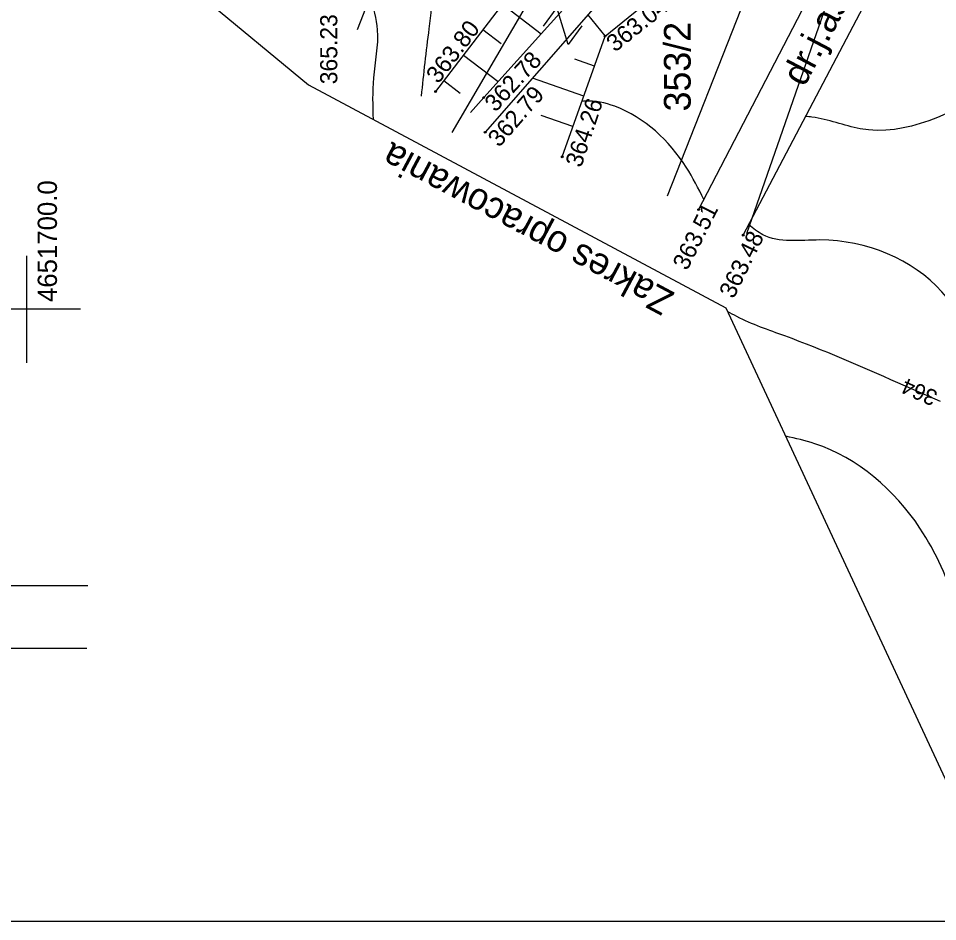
# Model space of a CAD drawing. Extents: x 4635329 to 4651863, y 5356628 to 5367582.
# Drawn here: x 4651136.61 to 4651179.57, y 5356627.73 to 5356669.94 of the extents above; entities that cross this region are included whole.
import ezdxf

# ---------------------------------------------------------------- set-up
doc = ezdxf.new("R2010")
doc.units = 0
for name, color, linetype in [('Level 1', 7, 'Continuous'), ('Level 13', 7, 'Continuous'), ('Level 20', 7, 'Continuous'), ('Level 21', 7, 'Continuous'), ('Level 4', 7, 'Continuous'), ('Level 44', 7, 'Continuous'), ('Level 45', 7, 'Continuous'), ('Level 46', 7, 'Continuous'), ('Level 47', 7, 'Continuous'), ('Level 48', 7, 'Continuous'), ('Level 5', 7, 'Continuous'), ('Level 50', 7, 'Continuous'), ('Level 53', 7, 'Continuous'), ('Level 58', 7, 'Continuous'), ('Level 6', 7, 'Continuous'), ('Level 60', 7, 'Continuous')]:
    doc.layers.add(name, color=color, linetype=linetype)

msp = doc.modelspace()

# ---------------------------------------------------------------- linework, layer by layer
at = {"layer": 'Level 1'}
for p, q in [((4651116.718, 5356694.556), (4651150.17, 5356666.828)), ((4651150.17, 5356666.828), (4651169.678, 5356656.408)), ((4651169.678, 5356656.408), (4651180.231, 5356633.731))]:
    msp.add_line(p, q, dxfattribs=at)
at = {"layer": 'Level 13'}
for p, q in [((4651124.206, 5356643.431), (4651139.857, 5356643.431)), ((4651124.168, 5356640.504), (4651139.819, 5356640.504))]:
    msp.add_line(p, q, dxfattribs=at)
msp.add_lwpolyline([(4651092.18, 5356627.729), (4651092.18, 5356813.355), (4651331.195, 5356813.355), (4651331.195, 5356627.729)], close=True, dxfattribs=at)
at = {"layer": 'Level 20'}
for points in [[(4651168.395, 5356660.997), (4651177.845, 5356679.207), (4651179.215, 5356683.117), (4651178.934, 5356685.139), (4651178.315, 5356686.247)], [(4651170.485, 5356659.807), (4651180.145, 5356678.177), (4651182.105, 5356681.997), (4651184.185, 5356684.287), (4651185.485, 5356685.017)], [(4651155.343, 5356676.839), (4651152.438, 5356669.398)]]:
    msp.add_lwpolyline(points, dxfattribs=at)
at = {"layer": 'Level 4'}
for p, q in [((4651169.904, 5356686.914), (4651156.863, 5356664.599)), ((4651175.849, 5356684.307), (4651166.932, 5356661.628)), ((4651178.797, 5356683.326), (4651170.632, 5356659.869))]:
    msp.add_line(p, q, dxfattribs=at)
at = {"layer": 'Level 44'}
for centre in [(4651164.025, 5356669.107), (4651156.105, 5356666.517), (4651158.355, 5356666.237), (4651158.425, 5356664.617), (4651162.025, 5356663.467), (4651168.395, 5356660.997), (4651170.485, 5356659.807)]:
    msp.add_circle(centre, 0.04, dxfattribs=at)
at = {"layer": 'Level 46'}
msp.add_line((4651179.706, 5356652.031), (4651177.706, 5356652.91), dxfattribs=at)
for points in [[(4651186.942, 5356655.734), (4651186.443, 5356658.066), (4651187.231, 5356661.219), (4651188.565, 5356664.25), (4651188.99, 5356667.342), (4651189.172, 5356670.677), (4651183.41, 5356675.407), (4651180.62, 5356675.589), (4651178.861, 5356675.735)], [(4651155.447, 5356666.303), (4651155.811, 5356669.456), (4651155.871, 5356671.396), (4651155.144, 5356672.972), (4651154.276, 5356674.106)], [(4651153.044, 5356670.951), (4651153.385, 5356669.395), (4651153.203, 5356667.152), (4651153.191, 5356665.214)], [(4651182.363, 5356666.668), (4651175.94, 5356664.78), (4651173.696, 5356665.325), (4651173.402, 5356665.355)], [(4651168.644, 5356661.477), (4651167.822, 5356662.977), (4651164.487, 5356665.827), (4651163.092, 5356666.069), (4651162.943, 5356666.056)], [(4651184.591, 5356650.319), (4651183.228, 5356652.73), (4651181.348, 5356655.034), (4651179.771, 5356657.156), (4651174.07, 5356659.581), (4651171.401, 5356659.824), (4651170.74, 5356660.291)], [(4651177.706, 5356652.91), (4651172.432, 5356655.095), (4651170.188, 5356656.004), (4651169.755, 5356656.242)], [(4651181.627, 5356637.725), (4651181.408, 5356639.209), (4651180.499, 5356642.422), (4651178.74, 5356646.121), (4651173.827, 5356650.062), (4651172.468, 5356650.413)]]:
    msp.add_spline(points, degree=3, dxfattribs=at)
at = {"layer": 'Level 48'}
for p, q in [((4651159.227, 5356670.605), (4651161.04, 5356669.22)), ((4651164.037, 5356669.117), (4651163.227, 5356670.115)), ((4651158.317, 5356669.413), (4651159.175, 5356668.757)), ((4651157.406, 5356668.221), (4651159.026, 5356666.983)), ((4651163.529, 5356667.708), (4651162.611, 5356668.034)), ((4651156.496, 5356667.029), (4651157.261, 5356666.444)), ((4651163.028, 5356666.294), (4651160.632, 5356667.144)), ((4651162.526, 5356664.881), (4651161.049, 5356665.405))]:
    msp.add_line(p, q, dxfattribs=at)
for points in [[(4651174.025, 5356685.027), (4651167.745, 5356676.767), (4651160.505, 5356672.277), (4651156.105, 5356666.517)], [(4651162.025, 5356663.467), (4651164.025, 5356669.107), (4651169.234, 5356673.337), (4651174.905, 5356676.627), (4651178.385, 5356683.247)]]:
    msp.add_lwpolyline(points, dxfattribs=at)
at = {"layer": 'Level 50'}
for points in [[(4651157.745, 5356665.536), (4651158.355, 5356666.237), (4651163.035, 5356671.437), (4651170.955, 5356676.617), (4651175.165, 5356684.237)], [(4651176.225, 5356683.677), (4651172.695, 5356677.237), (4651171.383, 5356675.905), (4651163.465, 5356670.387), (4651158.425, 5356664.617)]]:
    msp.add_lwpolyline(points, dxfattribs=at)
at = {"layer": 'Level 53'}
for p, q in [((4651161.774, 5356670.442), (4651161.137, 5356669.57)), ((4651162.3, 5356668.722), (4651161.774, 5356670.442)), ((4651162.937, 5356669.594), (4651162.3, 5356668.722))]:
    msp.add_line(p, q, dxfattribs=at)
at = {"layer": 'Level 60'}
for p, q in [((4651137.015, 5356653.847), (4651137.015, 5356658.847)), ((4651139.515, 5356656.347), (4651134.515, 5356656.347))]:
    msp.add_line(p, q, dxfattribs=at)

# ---------------------------------------------------------------- texts
at = {"layer": 'Level 21'}
msp.add_text('dr.j.asf. ', height=1.25, rotation=62.262, dxfattribs=at).set_placement((4651173.339, 5356666.695))
at = {"layer": 'Level 45'}
for s, rotation, p in [('363.04', 38.461, (4651164.49, 5356668.328)), ('365.23', 90, (4651151.515, 5356666.858)), ('363.80', 52.7649, (4651156.238, 5356666.847)), ('362.78', 47.4828, (4651158.91, 5356665.521)), ('362.79', 48.6813, (4651159.077, 5356663.876)), ('364.26', 71.6462, (4651162.91, 5356662.93)), ('363.51', 63.1803, (4651167.86, 5356658.117)), ('363.48', 63.9169, (4651170.036, 5356656.798))]:
    msp.add_text(s, height=0.8, rotation=rotation, dxfattribs=at).set_placement(p)
at = {"layer": 'Level 47'}
msp.add_text('364', height=0.75, rotation=156.2946, dxfattribs=at).set_placement((4651179.628, 5356652.481))
at = {"layer": 'Level 5'}
msp.add_text('353/2', height=1.25, rotation=90, dxfattribs=at).set_placement((4651168.028, 5356665.589))
at = {"layer": 'Level 58'}
msp.add_text(' 4651700.0 ', height=0.9, rotation=90, dxfattribs=at).set_placement((4651138.415, 5356656.347))
at = {"layer": 'Level 6'}
msp.add_text('Zakres opracowania', height=1.25, rotation=151.8916, dxfattribs=at).set_placement((4651167.331, 5356657.095))

doc.saveas('drawing.dxf')
